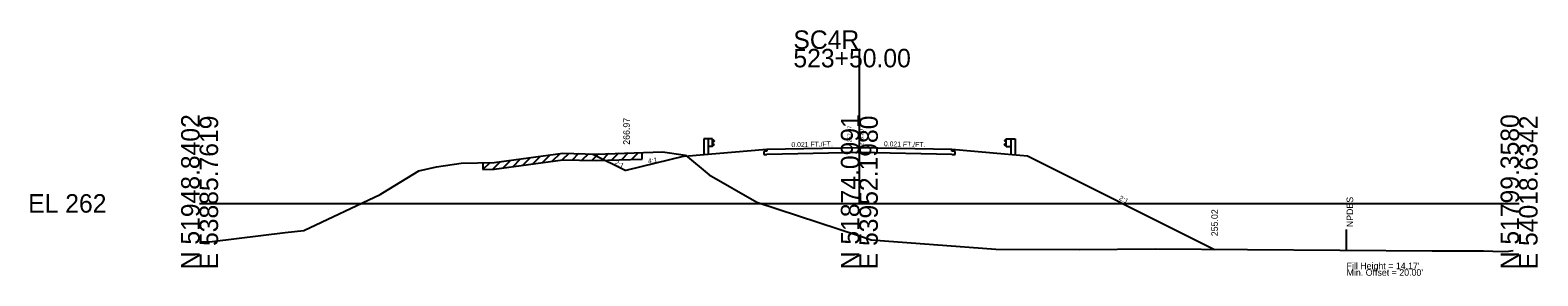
# Model space of a CAD drawing. Extents: x 7498 to 13027, y 90095 to 109625.
# Drawn here: x 9498.3 to 9726.8, y 93594.2 to 93631.4 of the extents above; entities that cross this region are included whole.
import ezdxf

# ---------------------------------------------------------------- set-up
doc = ezdxf.new("R2010")
doc.units = 0
for name, color, linetype in [('Level 10', 7, 'Continuous'), ('Level 11', 7, 'Continuous'), ('Level 12', 7, 'Continuous'), ('Level 24', 7, 'Continuous'), ('Level 32', 7, 'Continuous'), ('Level 33', 7, 'Continuous'), ('Level 50', 7, 'Continuous'), ('Level 55', 7, 'Continuous'), ('Level 59', 7, 'Continuous'), ('Level 6', 7, 'Continuous'), ('Level 60', 7, 'Continuous'), ('Level 61', 7, 'Continuous'), ('Level 63', 7, 'Continuous'), ('Level 7', 7, 'Continuous')]:
    doc.layers.add(name, color=color, linetype=linetype)

msp = doc.modelspace()

# ---------------------------------------------------------------- linework, layer by layer
at = {"layer": 'Level 11'}
for p, q in [((9609.99, 93613.37), (9609.99, 93613.07)), ((9637.99, 93613.07), (9637.99, 93613.37)), ((9609.99, 93613.07), (9609.49, 93613.05)), ((9609.49, 93613.05), (9609.49, 93612.57)), ((9609.49, 93612.57), (9609.99, 93612.59)), ((9638.49, 93613.05), (9637.99, 93613.07)), ((9637.99, 93612.59), (9638.49, 93612.57)), ((9638.49, 93612.57), (9638.49, 93613.05))]:
    msp.add_line(p, q, dxfattribs=at)
at = {"layer": 'Level 12'}
for p, q in [((9623.99, 93612.88), (9609.99, 93612.59)), ((9637.99, 93612.59), (9623.99, 93612.88))]:
    msp.add_line(p, q, dxfattribs=at)
at = {"layer": 'Level 24'}
for p, q in [((9601.06, 93614.94), (9600.4, 93614.94)), ((9600.4, 93614.94), (9600.4, 93612.53)), ((9601.73, 93614.94), (9601.06, 93614.94)), ((9601.06, 93614.94), (9601.06, 93612.6)), ((9601.73, 93613.78), (9601.06, 93613.78)), ((9601.73, 93613.78), (9601.73, 93614.94)), ((9601.73, 93614.87), (9602, 93614.67)), ((9602, 93614.62), (9601.73, 93614.42)), ((9602, 93614.1), (9601.73, 93614.3)), ((9601.73, 93613.85), (9602, 93614.05)), ((9602, 93614.67), (9602, 93614.62)), ((9602, 93614.05), (9602, 93614.1)), ((9646.26, 93614.88), (9645.99, 93614.68)), ((9645.99, 93614.68), (9645.99, 93614.63)), ((9645.99, 93614.63), (9646.26, 93614.43)), ((9645.99, 93614.1), (9646.26, 93614.3)), ((9645.99, 93614.05), (9645.99, 93614.1)), ((9646.26, 93613.85), (9645.99, 93614.05)), ((9646.26, 93613.78), (9646.26, 93614.95)), ((9646.26, 93614.95), (9646.93, 93614.95)), ((9646.26, 93613.78), (9646.93, 93613.78)), ((9646.93, 93614.95), (9646.93, 93612.6)), ((9646.93, 93614.95), (9647.6, 93614.95)), ((9647.6, 93614.95), (9647.6, 93612.54))]:
    msp.add_line(p, q, dxfattribs=at)
at = {"layer": 'Level 55'}
msp.add_line((9697.84, 93598.18), (9697.84, 93601.18), dxfattribs=at)
at = {"layer": 'Level 59'}
for p, q in [((9609.99, 93613.37), (9623.99, 93613.66)), ((9623.99, 93613.66), (9637.99, 93613.37))]:
    msp.add_line(p, q, dxfattribs=at)
at = {"layer": 'Level 6'}
for p, q in [((9597.49, 93612.32), (9609.99, 93613.37)), ((9637.99, 93613.37), (9645.99, 93612.7)), ((9645.99, 93612.7), (9649.49, 93612.35))]:
    msp.add_line(p, q, dxfattribs=at)
at = {"layer": 'Level 60'}
for p, q in [((9559.88, 93610.72), (9563.64, 93611.24)), ((9563.64, 93611.24), (9568.66, 93611.34)), ((9568.66, 93611.34), (9579.03, 93612.76)), ((9579.03, 93612.76), (9584.12, 93612.65)), ((9584.12, 93612.65), (9594.13, 93612.97)), ((9594.13, 93612.97), (9597.66, 93612.46)), ((9597.66, 93612.46), (9601.23, 93609.51)), ((9551.76, 93606.75), (9557.21, 93610.1)), ((9557.21, 93610.1), (9559.88, 93610.72)), ((9601.23, 93609.51), (9608.47, 93605.33)), ((9539.81, 93601.06), (9551.34, 93606.5)), ((9551.34, 93606.5), (9551.76, 93606.75)), ((9608.47, 93605.33), (9623.99, 93600.23)), ((9525.87, 93599.39), (9536.97, 93600.72)), ((9536.97, 93600.72), (9539.81, 93601.06)), ((9623.99, 93600.23), (9625.77, 93599.64)), ((9625.77, 93599.64), (9644.68, 93598.21)), ((9523.99, 93599.31), (9525.87, 93599.39)), ((9644.68, 93598.21), (9657.36, 93598.16)), ((9657.36, 93598.16), (9668.84, 93598.24)), ((9668.84, 93598.24), (9710.8, 93597.94)), ((9710.8, 93597.94), (9718.61, 93597.94)), ((9718.61, 93597.94), (9721.43, 93597.84)), ((9721.43, 93597.84), (9722.4, 93597.91)), ((9722.4, 93597.91), (9723.1, 93597.99))]:
    msp.add_line(p, q, dxfattribs=at)
at = {"layer": 'Level 61'}
for p, q in [((9567.96, 93611.33), (9566.94, 93610.31)), ((9566.94, 93611.31), (9566.94, 93610.31)), ((9569.56, 93611.47), (9568.44, 93610.34)), ((9568.66, 93610.34), (9579.03, 93611.76)), ((9571.09, 93611.68), (9569.94, 93610.52)), ((9572.59, 93611.88), (9571.44, 93610.72)), ((9574.09, 93612.09), (9572.94, 93610.93)), ((9575.59, 93612.29), (9574.44, 93611.13)), ((9577.09, 93612.5), (9575.94, 93611.34)), ((9578.59, 93612.7), (9577.44, 93611.54)), ((9579.93, 93612.74), (9578.94, 93611.75)), ((9579.03, 93611.76), (9584.12, 93611.65)), ((9581.41, 93612.71), (9580.44, 93611.73)), ((9582.91, 93612.68), (9581.94, 93611.7)), ((9584.43, 93612.66), (9583.44, 93611.66)), ((9584.12, 93611.65), (9591.07, 93611.87)), ((9585.97, 93612.71), (9584.94, 93611.68)), ((9587.47, 93612.76), (9586.44, 93611.72)), ((9588.97, 93612.81), (9587.94, 93611.77)), ((9590.47, 93612.85), (9589.44, 93611.82)), ((9591.07, 93611.87), (9591.07, 93612.87)), ((9566.94, 93610.31), (9568.66, 93610.34))]:
    msp.add_line(p, q, dxfattribs=at)
at = {"layer": 'Level 63'}
for p, q in [((9623.99, 93605.16), (9623.99, 93628.6)), ((9523.99, 93605.16), (9623.99, 93605.16)), ((9623.99, 93605.16), (9723.99, 93605.16))]:
    msp.add_line(p, q, dxfattribs=at)
at = {"layer": 'Level 7'}
for p, q in [((9583.6, 93612.61), (9588.57, 93610.13)), ((9597.49, 93612.32), (9588.57, 93610.13)), ((9649.49, 93612.35), (9677.84, 93598.18))]:
    msp.add_line(p, q, dxfattribs=at)

# ---------------------------------------------------------------- texts
at = {"layer": 'Level 10'}
msp.add_text('257.07', height=0.6, rotation=90, dxfattribs=at).set_placement((9622.82, 93614.41))
at = {"layer": 'Level 32'}
for s, rotation, p in [('0.021 FT./FT.', 1.1916, (9613.7, 93613.69)), ('0.021 FT./FT.', 358.8084, (9627.71, 93613.83)), ('2:1', 333.435, (9586.8, 93611.11)), ('4:1', 9.4623, (9592.01, 93611.18)), ('2:1', 333.435, (9663.27, 93605.74))]:
    msp.add_text(s, height=0.75, rotation=rotation, dxfattribs=at).set_placement(p)
at = {"layer": 'Level 33'}
for s, p in [('266.97', (9589.2, 93614.05)), ('255.02', (9678.34, 93600.18))]:
    msp.add_text(s, height=1, rotation=90, dxfattribs=at).set_placement(p)
at = {"layer": 'Level 50'}
msp.add_text(' NPDES', height=1, rotation=90, dxfattribs=at).set_placement((9698.84, 93601.18))
for s, p in [("Fill Height = 14.17' ", (9697.84, 93595.18)), ("Min. Offset = 20.00' ", (9697.84, 93594.18))]:
    msp.add_text(s, height=1, dxfattribs=at).set_placement(p)
at = {"layer": 'Level 59'}
msp.add_text(' 270.50', height=0.6, rotation=90, dxfattribs=at).set_placement((9624.59, 93613.66))
at = {"layer": 'Level 63'}
for s, p in [('SC4R', (9613.99, 93628.6)), ('523+50.00', (9613.99, 93625.8)), ('EL 262', (9498, 93603.76))]:
    msp.add_text(s, height=2.8, dxfattribs=at).set_placement(p)
for s, p in [('N 51948.8402', (9523.99, 93595.16)), ('E 53885.7619', (9526.79, 93595.16)), ('N 51874.0991', (9623.99, 93595.16)), ('E 53952.1980', (9626.79, 93595.16)), ('N 51799.3580', (9723.99, 93595.16)), ('E 54018.6342', (9726.79, 93595.16))]:
    msp.add_text(s, height=2.8, rotation=90, dxfattribs=at).set_placement(p)

doc.saveas('drawing.dxf')
